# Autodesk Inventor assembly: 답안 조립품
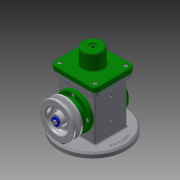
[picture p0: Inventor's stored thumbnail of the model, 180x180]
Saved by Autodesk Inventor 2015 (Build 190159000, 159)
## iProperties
Created: 2019-08
Part Number: 답안 조립품
Document SubType Name: Assembly
Designer: now
Author: now
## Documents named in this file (18)
- C:\Users\now\Desktop\490804V1025\답안 조립품.iam
- C:\Users\now\Desktop\490804V1025\E-링.ipt
- C:\Users\now\Desktop\490804V1025\V-벨트풀리.ipt
- C:\Users\now\Desktop\490804V1025\덮개.ipt
- C:\Users\now\Desktop\490804V1025\뒤커버.ipt
- C:\Users\now\Desktop\490804V1025\링크.ipt
- C:\Users\now\Desktop\490804V1025\베어링 17 x 40 x 12.ipt
- C:\Users\now\Desktop\490804V1025\본체.ipt
- C:\Users\now\Desktop\490804V1025\볼트 M4 x 8.ipt
- C:\Users\now\Desktop\490804V1025\볼트 M4 x 10.ipt
- C:\Users\now\Desktop\490804V1025\슬라이더.ipt
- C:\Users\now\Desktop\490804V1025\앞커버.ipt
- C:\Users\now\Desktop\490804V1025\오일 실 17 30 8.ipt
- C:\Users\now\Desktop\490804V1025\와셔 4x16.ipt
- C:\Users\now\Desktop\490804V1025\클레비스 핀 6 x 22.ipt
- 클레비스 핀 6 x 22.ipt
- C:\Users\now\Desktop\490804V1025\키 4 x 4 x 12.ipt
- C:\Users\now\Desktop\490804V1025\편심축.ipt
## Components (2 placed, 2 different names)
1. E-링:1
2. V-벨트풀리:1 — 각도:2
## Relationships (1: Angle 1)
- 각도:2 [Angle]: V-벨트풀리:1
